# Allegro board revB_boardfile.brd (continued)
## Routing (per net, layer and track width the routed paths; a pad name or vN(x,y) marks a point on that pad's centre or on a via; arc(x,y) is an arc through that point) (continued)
GND: length 4.7
  BOTTOM w0.305: v1(27.11,56.13) C82.1 25.58,55.53 25.58,55.42 25.27,55.12 24.31,55.12 23.92,54.73 U14.4
  vias: v1(2.35,42.32) v1(2.35,41.69) v1(2.35,41.05) v1(3.11,42.32) v1(3.87,42.32) v1(4.76,42.32) v1(4.76,41.69) v1(4.76,41.05) v1(5.52,42.32) v1(6.29,42.32) v1(7.05,42.32) v1(7.05,41.69) v1(7.05,41.05) v1(9.21,55.53) v1(9.97,55.53) v1(10.86,55.53) v1(11.75,55.53) v1(12.64,56.68) v1(12.64,55.53) v1(14.41,57.31) v1(14.41,56.68) v1(15.18,57.31) v1(15.18,56.68) v1(16.82,50.04) v1(16.82,49.02) v1(17.45,50.04) v1(17.45,49.02) v1(18.22,50.07) v1(18.22,49.56) v1(18.22,49.06) v1(20.89,45.75) v1(21.53,45.75) v1(22.16,45.75) v1(22.54,52.93) v1(22.54,52.48) v1(22.54,52.04) v1(22.54,51.6) v1(22.54,51.15) v1(22.54,50.71) v1(22.8,45.75) v1(23.02,52.93) v1(23.02,52.48) v1(23.02,52.04) v1(23.02,51.6) v1(23.02,51.15) v1(23.02,50.71) v1(23.43,45.75) v1(23.49,52.93) v1(23.49,52.48) v1(23.49,52.04) v1(23.49,51.6) v1(23.49,51.15) v1(23.49,50.71) v1(24.07,45.75) v1(24.7,45.75) v1(25.34,45.75) v1(25.97,45.75) v1(26.61,45.75) v1(27.23,52.07) v1(27.23,51.43) v1(27.23,50.8) v1(27.23,50.16) v1(27.23,49.53) v1(27.23,48.89) v1(27.23,48.26) v1(27.23,47.62) v1(27.23,46.35) v1(27.24,45.75) v1(27.62,46.77) v1(27.88,45.75) v1(28.38,45.75)
AD9361_AUXADC: length 33.3
  BOTTOM w0.305: P1.5 39.18,29.12 34.23,29.12 33.59,29.75 33.59,34.45 29.53,38.51 22.03,38.51 20.51,36.99 18.73,36.99 17.36,35.62 P2.19
AD9361_AUXDAC1: length 35.1
  BOTTOM w0.305: P1.7 41.59,28.99 40.83,28.99 40.32,28.48 33.84,28.48 32.96,29.37 32.96,34.2 29.27,37.88 22.29,37.88 20.76,36.36 18.99,36.36 18.16,35.53 P2.21
AD9361_AUXDAC2: length 39
  BOTTOM w0.305: P2.23 18.96,35.42 19.27,35.72 21.14,35.72 22.67,37.24 29.02,37.24 32.32,33.94 32.32,29.12 33.59,27.85 40.7,27.85 41.21,28.35 42.99,28.35 44.26,29.62 44.26,30.89 43.75,31.4 43.75,32.16 P1.8
AD9361_GPO0: length 55.8
  L3_PWR w0.305: v1(13.36,36.74) 13.36,35.9 14.05,35.21 14.79,35.21 16.83,37.24 28.51,37.24 P1.1 36.13,31.15 36.13,31.91 36.64,32.42 36.64,35.97 42.61,41.94 42.61,43.34 47.31,48.04 48.7,48.04 v1(49.47,48.8)
  BOTTOM w0.203: U16.12 49.2,48.54 v1(49.47,48.8)
  BOTTOM w0.305: P2.9 v1(13.36,36.74)
AD9361_GPO0_5V: length 22.6
  BOTTOM w0.203: U16.11 48.7,49.06 49.21,49.56 57.8,49.56 58.71,48.65 58.71,41.49 57.28,40.05 U30.5
AD9361_GPO1: length 48
  L3_PWR w0.305: v1(47.31,48.65) 46.82,48.65 41.97,43.8 41.97,42.32 35.37,35.72 P1.2 34.23,32.93 29.27,37.88 16.11,37.88 v1(14.16,35.93)
  BOTTOM w0.203: v1(47.31,48.65) 47.7,48.25 U16.9
  BOTTOM w0.305: P2.11 v1(14.16,35.93)
AD9361_GPO1_5V: length 16.4
  BOTTOM w0.203: U30.1 52.41,36.84 45.4,43.85 45.4,46.26 46.15,47.01 U16.8
AD9361_GPO2: length 50.4
  L3_PWR w0.305: v1(48.2,43.72) 46.67,43.72 39.18,36.23 39.18,31.66 P1.3
  BOTTOM w0.203: v1(48.2,43.72) 48.2,43.73 U16.5
  BOTTOM w0.305: P2.13 14.96,35.35 17.23,37.63 20.26,37.63 21.78,39.15 30.03,39.15 34.48,34.7 35.88,34.7 36.51,34.07 36.51,31.78 P1.3
AD9361_GPO2_5V: length 15.9
  BOTTOM w0.203: 56.2,37.88 56.24,37.84 U30.6 ; 56.2,37.88 56.2,37.85 55.68,37.34 U30.2 ; 56.2,37.88 56.2,39.53 53.91,41.82 49.21,41.82 47.7,43.32 U16.6
AD9361_GPO3: length 50.3
  L3_PWR w0.305: v1(15.76,35.21) 17.16,36.61 27.88,36.61 32.96,31.53 32.96,30.51 34.35,29.12 36,29.12 36.64,29.75 36.64,31.66 P1.4 37.91,35.97 46.42,44.48 49.34,44.48 v1(49.97,43.85)
  BOTTOM w0.203: v1(49.97,43.85) 49.7,44.12 U16.2
  BOTTOM w0.305: P2.15 v1(15.76,35.21)
AD9361_GPO3_5V: length 90.9
  TOP w0.305: U6.2 v2(84.3,20.67) ; U11.2 v2(84.33,45.82)
  L3_PWR w0.508: v2(84.33,45.82) 82.93,44.42 76.45,44.42 69.85,37.82 65.47,37.82 v1(62.8,40.48) 61.21,42.07 50.42,42.07 v1(49.78,42.71)
  BOTTOM w0.203: U16.3 49.2,43.28 v1(49.78,42.71)
  BOTTOM w0.356: v2(84.3,20.67) 84.3,20.7 76.3,20.7 75.37,21.62 75.37,33.05 74.29,34.13 74.29,39.85 80.27,45.82 v2(84.33,45.82)
  BOTTOM w0.508: R29.2 64.07,35.76 64.07,39.21 v1(62.8,40.48)
RF_3V3: length 7.2
  BOTTOM w0.508: P2.12 14.16,27.7 13.9,27.43 13.36,27.43 ; R15.1 13.1,25.84 13.36,26.11 13.36,27.43 ; 13.36,27.43 P2.10
RF_5V0: length 5.2
  BOTTOM w0.457: 10.96,32.48 P2.3 ; 11.76,32.48 P2.5 ; P2.4 10.96,30.7 ; P2.6 11.76,30.7
RF_12V0: length 5.9
  BOTTOM w0.508: v1(24.56,27.86) P2.38 24.57,29.4 v1(24.57,30.77) v1(24.57,31.4) v1(24.57,32.04) 24.57,33.78 P2.37
  vias: v1(12.76,42.32) v1(12.76,41.69) v1(13.4,42.32) v1(13.4,41.69) v1(24.57,28.48)
RF_GPIO0: length 91.6
  L3_PWR w0.305: v1(39.31,43.09) 45.66,49.44 50.1,49.44 55.05,44.48 58.36,44.48 61.4,47.53 62.24,47.53 62.55,47.23 62.55,41.75 65.66,38.64 v1(67.12,38.64)
  BOTTOM w0.203: v1(67.12,38.64) 67.34,38.42 U4.3
  BOTTOM w0.305: P2.31 22.16,33.79 22.16,35.85 22.92,36.61 28.76,36.61 31.69,33.69 31.69,28.86 33.34,27.21 43.88,27.21 45.53,28.86 P1.9 44.39,31.53 44.39,38.01 v1(39.31,43.09)
RF_GPIO0_5V: length 33.8
  TOP w0.381: C57.1 C58.1 v2(68.76,56.16) 68.76,55.42 68.77,55.41
  BOTTOM w0.508: v2(68.76,56.16) 69.79,57.18 72.76,57.18 75.06,54.88 75.06,43.86 73.47,42.27 73.47,36.56 72.64,35.73 U15.6
RF_GPIO1: length 37.9
  BOTTOM w0.305: P2.33 22.96,35.38 23.56,35.97 28.51,35.97 31.05,33.43 31.05,28.61 33.08,26.58 44.39,26.58 46.8,28.99 46.8,31.66 P1.10
RF_GPIO1_5V: length 12.4
  TOP w0.254: C25.1 68.76,29.47 v2(68.77,29.46) 68.76,29.45 C28.1 68.76,27.07 R8.1
  BOTTOM w0.305: U15.4 68.63,35.33 68.93,35.02 70.15,35.02 70.74,34.44 70.74,33.31 70.36,32.93 69.72,32.93 69.28,32.48 69.28,29.97 v2(68.77,29.46)
RF_GPIO2: length 35.1
  BOTTOM w0.305: P1.11 48.07,28.86 45.15,25.94 32.83,25.94 30.42,28.35 30.42,33.18 28.26,35.34 24.07,35.34 23.76,35.03 P2.35
RF_GPIO_012_VDD: length 95.2
  L3_PWR w0.305: v1(71.31,40.34) 71.31,40.1 69.62,38.41 68.24,38.41 67.37,39.28 65.92,39.28 63.18,42.02 63.18,47.53 62.61,48.1 61.08,48.1 58.09,45.12 55.32,45.12 50.36,50.07 45.27,50.07 33.72,38.51 13.65,38.51 12.51,37.37 12.51,35.72 13.78,34.45 20.38,34.45 v1(21.14,35.21)
  BOTTOM w0.305: v1(21.14,35.21) 21.36,35 P2.29 ; U4.5 66.73,39.07 67.38,39.72 68.06,39.72 U4.1
  BOTTOM w0.356: C94.2 69.66,40.67 68.71,39.72 U4.1
  BOTTOM w0.406: v1(71.31,40.34) 71.64,40.67
  BOTTOM w0.508: C94.2 C93.2
RX: length 33.3
  TOP w0.305: 87.69,45.16 U11.4 ; 87.69,20.01 U6.4
  TOP w0.33: v2(89.86,20.06) 88.83,20.06 ; 88.83,20.06 C39.2 ; 88.83,20.06 L6.1 ; 88.83,20.06 88.15,20.06 88.1,20.01 87.69,20.01 ; v2(89.65,43.41) C69.2 L11.1 88.64,45.16 87.69,45.16
  L3_PWR w0.254: v2(89.86,20.06) 90.49,20.69 90.49,33.82 89.65,34.65 v2(89.65,43.41)
TX: length 5.7
  TOP w0.254: 80.43,50.95 T2.6
  TOP w0.33: 80.43,50.95 81.28,50.95 arc(82.76,50.34) 83.37,48.85 83.37,48.47 83.36,48.46 C65.1
UNNAMED_2_ADHMC546_I144_ACG: length 1.6
  TOP w0.305: U11.3 84.49,45.16
  TOP w0.33: 84.49,45.16 83.54,45.16 C66.1
UNNAMED_2_ADHMC546_I144_RFC: length 9
  TOP w0.305: U11.6 87.72,46.48
  TOP w0.33: U11.6 87.08,47.46 arc(86.94,47.81) L10.2 ; 88.98,46.45 88.84,46.31 ; 88.98,46.45 C71.1 ; 88.98,46.45 88.96,46.48 88.64,46.48 ; 88.84,46.31 C91.1 ; 88.84,46.31 L11.2 88.64,46.48 ; 88.64,46.48 87.72,46.48
UNNAMED_2_ADHMC546_I144_TX: length 3.5
  TOP w0.305: 85.08,46.48 84.49,46.48
  TOP w0.33: 84.49,46.48 C65.2 ; U11.1 85.08,46.48 85.08,47.4 arc(85.24,47.79) L10.1
UNNAMED_2_ADHMC669_I175_ACG: length 2.1
  TOP w0.254: C3.1 79.72,40.97 78.89,40.14 U7.6
UNNAMED_2_ADHMC669_I175_RES: length 2.2
  TOP w0.254: R2.1 78.39,40.34 U7.7
UNNAMED_2_ADHMC669_I175_RFIN: length 11.8
  TOP w0.254: 80.67,38.09 U7.3
  TOP w0.33: C69.1 88.84,42.14 88.84,40.55 arc(88.12,38.81) 86.38,38.09 80.67,38.09
UNNAMED_2_ADHMC669_I175_RFOUT: length 53.5
  TOP w0.254: 76.68,38.09 U7.10
  TOP w0.33: 76.68,38.09 53.63,38.09 53.62,38.11 D2.3 52.01,38.11 52,38.1 FL2.4
UNNAMED_2_ADHMC669_I175_VCTL: length 35.1
  TOP w0.203: U7.16 79.94,36.41 80.2,36.15 v2(80.2,35.72) C51.1
  L3_PWR w0.254: v2(80.2,35.72) 80.2,34.32 79.31,33.43 55.69,33.43 55.18,33.94 55.18,37.37 54.71,37.84 v1(53.78,37.84)
  BOTTOM w0.203: U30.3 v1(53.78,37.84)
UNNAMED_2_ADHMC669_I175_VDD: length 1.6
  TOP w0.254: U7.14 78.39,34.8 L8.1
UNNAMED_2_ADHMC921_I79_RFIN: length 1.1
  TOP w0.254: 65.63,50.19 U8.4
  TOP w0.33: 65.63,50.19 64.97,50.19 C52.2
UNNAMED_2_ADHMC921_I79_RFOUT: length 7.9
  TOP w0.254: C59.1 70.68,50.19 U8.15 ; U8.16 70.88,50.69 70.88,50.68 ; U8.17 70.93,51.19 70.93,51.19
  TOP w0.33: L9.1 71.83,50.96 C63.1 76.26,50.96
UNNAMED_2_ADHMC921_I79_VEN: length 1.8
  TOP w0.254: R4.2 68.75,54.11 U8.20
UNNAMED_2_ADL5324_I116_RFIN: length 3.7
  TOP w0.33: C42.2 C43.1 36.8,50.07 U10.1
UNNAMED_2_ADL5324_I116_RFOUT: length 23.8
  TOP w0.33: U10.3 41.27,50.17 41.29,50.19 L7.1 C49.1 62.41,50.19 C50.1 C52.1
UNNAMED_2_CAP_I99_N1: length 9.2
  TOP w0.33: FL1.2 24.53,46.9 arc(25.79,47.15) 26.86,47.86 28.17,49.17 arc(29.17,49.84) 30.34,50.07 C42.1
UNNAMED_2_CAP_I148_N2: length 4
  TOP w0.33: C71.2 93.58,46.5 RF_IO1.1
UNNAMED_2_CAP_I196_N2: length 1.7
  TOP w0.254: 78.73,50.95 T2.1
  TOP w0.33: 78.73,50.95 77.52,50.95 C64.2
UNNAMED_2_CNBNC3P_I83_CNTR: length 11.1
  TOP w0.33: TX1_A.1 FL1.4
UNNAMED_2_CNBNC3P_I86_CNTR: length 51.9
  TOP w0.305: R13.1 54.25,44.99
  TOP w0.33: TX1MON.1 7.82,42.45 arc(9.55,42.79) 11.01,43.77 arc(12.36,44.67) 13.95,44.99 54.25,44.99 ; R14.1 54.3,45.02 R13.1
UNNAMED_2_CNBNC3P_I158_CNTR: length 11.2
  TOP w0.33: RX1_A.1 10.22,38.1 FL2.2
UNNAMED_2_RES_I197_N1: length 1.7
  TOP w0.254: 79.97,49.62 T2.4
  TOP w0.33: R18.1 79.97,49.09 79.97,49.1 79.97,49.62
UNNAMED_2_RES_I198_N2: length 22.9
  TOP w0.254: T2.3 79.19,49.62
  TOP w0.33: R14.2 58.03,45.03 R16.1 60.02,45.04 70.34,45.04 arc(74.88,46.24) 78.73,48.93 79.02,49.23 arc(79.14,49.41) 79.19,49.62
UNNAMED_3_ADHMC546_I36_ACG: length 1.5
  TOP w0.305: 84.39,20.01 U6.3
  TOP w0.33: C36.1 83.54,20.01 84.39,20.01
UNNAMED_3_ADHMC546_I36_RFC: length 8.5
  TOP w0.305: 87.62,21.33 U6.6 87.03,21.75
  TOP w0.33: C40.1 88.84,21.33 ; 88.84,21.33 88.84,21.19 L6.2 ; 88.84,21.33 87.62,21.33 ; 88.84,21.33 C41.1 ; 87.03,21.75 87.03,22.25 arc(86.87,22.63) L5.2
UNNAMED_3_ADHMC546_I36_TX: length 3.4
  TOP w0.305: 84.47,21.33 U6.1 85.03,21.74
  TOP w0.33: C35.2 84.47,21.33 ; 85.03,21.74 85.03,22.29 arc(85.18,22.64) L5.1
UNNAMED_3_ADHMC669_I19_ACG: length 2.1
  TOP w0.254: C1.1 79.85,11.91 78.92,10.98 U2.6
UNNAMED_3_ADHMC669_I19_RES: length 2.2
  TOP w0.254: U2.7 78.42,11.39 R1.1
UNNAMED_3_ADHMC669_I19_RFIN: length 15
  TOP w0.254: 80.69,9.04 U2.3
  TOP w0.33: 80.69,9.04 84.76,9.04 arc(87.64,10.23) 88.84,13.11 88.84,17.02 C39.1
UNNAMED_3_ADHMC669_I19_RFOUT: length 53.8
  TOP w0.254: U2.10 76.53,9.04 76.52,9.02
  TOP w0.33: FL4.4 46.39,9.05 D1.3 76.52,9.02
UNNAMED_3_ADHMC669_I19_VCTL: length 55.6
  TOP w0.203: v2(79.82,4.88) 80.07,5.14 C14.1 79.74,6.1 79.74,6.56 79.42,6.89 U2.16
  BOTTOM w0.254: 66.48,3.59 78.52,3.59 v2(79.82,4.88)
  BOTTOM w0.305: 66.48,3.59 56.2,13.88 56.2,36.99 56.55,37.34 U30.7
UNNAMED_3_ADHMC669_I19_VDD: length 1.6
  TOP w0.254: U2.14 78.42,6.4 78.39,6.37 L3.1
UNNAMED_3_ADHMC921_I94_RFIN: length 1.1
  TOP w0.254: 65.63,21.85 U5.4
  TOP w0.33: 65.63,21.85 64.97,21.85 C15.2
UNNAMED_3_ADHMC921_I94_RFOUT: length 7.8
  TOP w0.254: U5.17 70.9,22.85 70.92,22.83 70.92,22.84 ; U5.16 70.76,22.35 ; U5.15 70.68,21.85 C29.1
  TOP w0.33: 71.61,22.61 C33.1 76.26,22.61
UNNAMED_3_ADHMC921_I94_VEN: length 1.8
  TOP w0.254: R8.2 68.75,25.77 U5.20
UNNAMED_3_ADL5324_I56_RFIN: length 3.7
  TOP w0.33: U9.1 35.89,21.85 C6.1 C5.2
UNNAMED_3_ADL5324_I56_RFOUT: length 24
  TOP w0.33: C15.1 C13.1 C12.1 L2.1 40.97,21.85 40.97,21.85 U9.3
UNNAMED_3_CAP_I35_N1: length 3.4
  TOP w0.254: 80.49,22.6 T1.6
  TOP w0.33: C35.1 80.49,22.6
UNNAMED_3_CAP_I45_N2: length 3.9
  TOP w0.33: RF_IO2.1 C41.2
UNNAMED_3_CAP_I53_N1: length 8.2
  TOP w0.33: FL3.2 C5.1
UNNAMED_3_CAP_I127_N2: length 1.6
  TOP w0.254: T1.1 78.69,22.6 78.68,22.61
  TOP w0.33: 78.68,22.61 C34.2
UNNAMED_3_CNBNC3P_I21_CNTR: length 46.2
  TOP w0.33: TX2MON.1 54.2,17.43 R5.1 56.15,17.52 R6.1
UNNAMED_3_CNBNC3P_I51_CNTR: length 16
  TOP w0.33: TX2_A.1 FL3.4
UNNAMED_3_CNBNC3P_I105_CNTR: length 17
  TOP w0.33: RX2_A.1 7.59,12.99 arc(10.14,12.48) 12.3,11.04 12.53,10.81 arc(14.48,9.51) 16.78,9.05 FL4.2
UNNAMED_3_RES_I126_N1: length 1.7
  TOP w0.254: 79.95,21.3 T1.4
  TOP w0.33: R9.1 79.95,20.75 79.95,20.75 79.95,21.3
UNNAMED_3_RES_I129_N1: length 22.4
  TOP w0.254: 78.6,21.29 78.89,21.59 T1.3
  TOP w0.33: R6.2 59.84,17.43 R7.1 59.89,17.41 70.22,17.41 arc(74.75,18.61) 78.6,21.29
UNNAMED_5_7445V2_I198_B: length 2.1
  BOTTOM w0.406: U4.4 65.25,37.85 R28.1
UNNAMED_5_ADM7171_I71_SS: length 2.1
  BOTTOM w0.305: U1.4 83.18,55.95 C2.1
UNNAMED_5_ADM7171_I103_SS: length 2.1
  BOTTOM w0.305: U12.4 83.18,28.75 83.36,28.93 C76.1
UNNAMED_5_ADP238X_I108_BST: length 7.5
  L3_PWR w0.305: v1(23.92,48.93) 23.29,48.29 21.12,48.29 v1(19.49,46.67)
  BOTTOM w0.305: C81.1 v1(19.49,46.67) ; U14.15 v1(23.92,48.93)
UNNAMED_5_ADP238X_I108_COMP: length 6.8
  BOTTOM w0.305: C86.1 17.35,56.19 18.18,55.37 18.18,55.22 18.91,54.48 C84.1 19.81,53.72 19.96,53.86 U14.1
UNNAMED_5_ADP238X_I108_EN: length 17
  BOTTOM w0.305: U14.20 12.76,51.06 11.86,50.16 R23.2 R21.2
UNNAMED_5_ADP238X_I108_FB: length 4.6
  BOTTOM w0.305: U14.2 22.92,54.6 22.34,55.18 R24.1 22.34,57.44 22.28,57.5 R25.2
UNNAMED_5_ADP238X_I108_PVIN1: length 8.2
  BOTTOM w0.305: C19.1 13.39,49.53 12.75,48.89 R23.1
UNNAMED_5_ADP238X_I108_RT: length 12.5
  BOTTOM w0.305: R22.1 10.28,51.69 20.25,51.69 20.62,52.06 U14.22
UNNAMED_5_ADP238X_I108_SS: length 10.5
  BOTTOM w0.305: C80.1 12.27,52.7 12.65,52.32 19.86,52.32 20.61,53.06 U14.24
UNNAMED_5_ADP238X_I108_SW1: length 11.8
  L3_PWR w0.305: v1(19.49,44.99) 19.49,45.88 21.27,47.66 23.56,47.66 v1(24.57,48.67)
  BOTTOM w0.305: v1(19.49,44.99) 19.27,44.76 C81.2 ; U14.PAD2 24.42,51.69 U14.14 24.42,48.82 v1(24.57,48.67)
UNNAMED_5_ADP238X_I108_VREG: length 2.7
  BOTTOM w0.305: C82.2 24.47,56.08 23.42,55.03 U14.3
UNNAMED_5_ADP7104_I52_SENSE: length 4.5
  BOTTOM w0.305: R10.2 81.13,42.46 81.08,42.42 R12.1 81.13,41.62 82.36,40.39 U3.2
UNNAMED_5_ADP7104_I92_SENSE: length 4.6
  BOTTOM w0.305: R19.2 81,13.16 81.08,13.08 R20.1 81.13,12.28 82.23,11.18 U13.2
UNNAMED_5_CAP_I117_N2: length 27.6
  L3_PWR w0.305: v1(19.36,56.13) 19.36,57.3 21.27,59.22 28.38,59.22 34.68,52.92 v1(34.68,49.69)
  BOTTOM w0.305: R27.2 C83.2 v1(34.68,49.69) ; R24.2 v1(19.36,56.13)
UNNAMED_5_CAP_I127_N2: length 2.5
  BOTTOM w0.305: C84.2 15.55,53.72 15.48,53.65 R26.1
UNNAMED_5_CAP_I146_N2: length 2.5
  BOTTOM w0.305: R3.1 16.88,39.4 16.84,39.37 C92.2
UNNAMED_5_DIOLED_I85_P: length 11.5
  TOP w0.305: DS1.A v2(2.72,29.76)
  BOTTOM w0.305: R15.2 10.21,26.07 6.41,26.07 v2(2.72,29.76)
UNNAMED_5_NC7WZ17P6X_I161_A1: length 6.2
  BOTTOM w0.305: 68.56,33.9 U15.3 ; 68.56,33.9 67.63,33.9 R29.1 ; 68.56,33.9 68.64,33.99 68.64,34.2 68.92,34.48 69.65,34.48 69.93,34.2 U15.1
  BOTTOM w0.406: R29.1 R28.2
VDET_HMC921_1: length 68.3
  TOP w0.254: C56.1 68.75,47.17 U8.11
  TOP w0.305: C56.1 62.17,47.15 v2(61.91,46.9)
  L3_PWR w0.305: v1(19.76,35.21) 20.52,35.97 27.37,35.97 32.07,31.28 32.07,30.26 33.97,28.35 36.51,28.35 37.27,29.12 41.08,29.12 41.72,29.75 41.72,37.75 45.78,41.82 48,41.82 49.53,43.34 58.36,43.34 v2(61.91,46.9)
  BOTTOM w0.305: P2.25 v1(19.76,35.21)
VDET_HMC921_2: length 56.5
  TOP w0.254: U5.11 68.75,18.98 C24.1
  TOP w0.305: v2(51.13,19.7) 60.56,19.7 61.43,18.83 68.64,18.83 C24.1
  BOTTOM w0.305: v2(51.13,19.7) 26.37,19.7 19.76,26.31 P2.26

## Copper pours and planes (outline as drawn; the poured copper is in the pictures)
5V5 on BOTTOM: 85.66,7.91 85.66,9.05 85.79,9.18 85.79,10.83 86.93,10.83 87.44,10.32 90.74,10.32 90.74,12.35 90.23,12.86 90.23,24.8 85.79,24.8 85.79,26.7 87.18,26.7 87.18,28.48 90.61,28.48 90.61,37.12 85.79,37.12 85.79,40.04 86.55,40.04 86.55,39.78 86.93,39.4 90.74,39.4 90.74,42.45 90.99,42.71 90.99,51.09 85.79,51.09 85.79,53.12 87.18,53.12 87.18,54.9 90.74,54.9 90.74,58.58 59.47,58.58 53.38,52.48 38.54,52.48 37.02,50.96 37.02,41.92 35.99,40.89 20.63,40.89 20.63,42.67 29.52,42.67 29.52,43.81 32.95,43.81 32.95,46.1 35.1,46.1 35.1,57.15 34.85,57.4 32.69,57.4 32.6,57.31 25.97,57.31 25.97,61.25 92.9,61.25 92.9,7.91
5V_3P3V_LNA1 on TOP: 74.48,34.07 77.41,34.07 77.41,35.59 76.26,35.59 76.26,36.86 75.75,37.37 74.48,37.37
5V_3P3V_LNA1 on BOTTOM: 58.48,36.99 56.7,36.99 56.7,34.7 57.34,34.07 62.42,34.07 62.93,34.58 62.93,36.86 62.42,37.37 58.48,37.37
5V_3P3V_LNA1 on BOTTOM: 83.5,39.91 83.5,36.86 82.87,36.23 80.07,36.23 80.07,34.32 79.82,34.07 75.25,34.07 74.67,34.64 74.67,38.26 79.44,38.26 79.44,40.17 79.69,40.42 81.85,40.42 82.23,40.04 83.37,40.04
5V_3P3V_LNA1 on L3_PWR: 55.94,38.7 55.94,34.07 88.45,34.07 88.84,34.45 88.84,39.53 88.33,40.04 86.8,40.04 83.37,43.47 76.01,43.47 70.29,37.75 65.28,37.75 63.37,39.66 56.89,39.66
5V_3P3V_LNA2 on TOP: 74.48,8.44 74.48,4.88 77.28,4.88 77.28,6.54 76.39,6.54 76.39,7.15 75.75,7.78 75.75,8.44
5V_3P3V_LNA2 on BOTTOM: 79.56,11.08 81.85,11.08 82.1,10.83 83.37,10.83 83.37,7.78 82.61,7.02 79.69,7.02 79.69,5.37 79.06,4.73 74.87,4.73 74.23,5.37 74.23,8.8 74.48,9.05 79.18,9.05 79.18,10.7
5V_3P3V_LNA2 on L3_PWR: 83.25,10.7 83.25,7.78 79.95,4.48 71.94,4.48 71.94,10.7
5V_PREAMP1 on TOP (solid shape): 76.77,56.04 73.79,56.04 73.79,56.07 73.09,56.07 73.09,56.93 73.09,57.44 73.09,58.07 76.77,58.07
5V_PREAMP1 on TOP: 86.23,42.26 86.23,43.98 87.88,43.98 87.88,40.67 86.55,40.67 86.55,41.94
5V_PREAMP1 on TOP: 67.12,53.37 65.34,53.37 64.83,53.88 64.83,56.42 64.45,56.8 64.45,59.09 66.61,59.09 67.12,58.58
5V_PREAMP1 on TOP: 40.32,57.95 40.32,56.04 41.46,54.9 41.46,51.21 42.48,51.21 42.48,55.53 42.86,55.91 42.86,58.2 42.61,58.45 40.83,58.45
5V_PREAMP1 on BOTTOM: 53.02,46.77 53.02,45.63 57.09,45.63 57.09,46.77
5V_PREAMP1 on BOTTOM: 83.5,53.63 83.5,48.55 78.68,48.55 78.68,53.63
5V_PREAMP1 on BOTTOM: 66.6,44.27 64.82,44.27 64.82,40.97 65.34,40.44 65.34,39.57 66.6,39.57
5V_PREAMP1 on L3_PWR: 88.84,41.56 88.33,41.05 86.8,41.05 85.03,42.83 85.03,46.01 84.64,46.39 84.01,46.39 82.87,45.25 76.01,45.25 69.91,39.15 66.1,39.15 63.75,41.5 63.75,47.34 62.8,48.29 61.4,48.29 58.36,45.25 56.7,45.25 56.51,45.44 56.07,45.44 51.05,50.45 44.77,50.45 42.23,47.91 38.92,47.91 38.92,61.25 87.95,61.25 88.84,60.36 ; 1 cut-out
5V_PREAMP2 on TOP (solid shape): 76.77,27.72 73.79,27.72 73.79,27.72 73.09,27.72 73.09,28.58 73.09,29.09 73.09,29.75 76.77,29.75
5V_PREAMP2 on TOP: 86.55,15.53 86.55,18.7 88.07,18.7 88.07,15.53
5V_PREAMP2 on TOP: 67.11,25.02 65.33,25.02 64.82,25.52 64.82,28.11 64.44,28.49 64.44,30.51 66.74,30.51 67.11,30.14
5V_PREAMP2 on TOP: 41.08,22.89 41.08,28.1 41.72,28.74 46.04,28.74 46.42,28.35 46.42,26.45 45.15,26.45 44.26,27.34 42.48,27.34 42.23,27.08 42.23,24.04 42.29,23.97 42.29,23.85 42.1,23.66 42.1,22.89
5V_PREAMP2 on BOTTOM: 83.5,27.08 83.5,22.51 78.8,22.51 78.8,27.21 82.61,27.21 82.74,27.08
5V_PREAMP2 on L3_PWR: 83.56,17.05 85.47,15.15 87.82,15.15 88.07,15.4 88.07,20.99 87.57,21.5 83.25,21.5 82.74,22 82.74,26.96 82.23,27.47 77.28,27.47 74.99,29.75 67.88,29.75 67.12,30.51 66.1,30.51 64.2,28.61 39.43,28.61 38.42,27.59 38.42,17.56 38.92,17.05 ; 4 cut-outs
AGND on TOP: 96.07,0.67 4,0.67 0.67,4 0.67,58.17 3.75,61.25 96.33,61.25 99.25,58.33 99.25,3.84 ; 24 cut-outs
AGND on BOTTOM: 90.87,41.44 87.69,41.44 87.31,41.05 85.66,41.05 85.28,41.44 85.28,40.29 85.66,40.67 86.93,40.67 86.93,39.91 87.06,39.78 90.87,39.78
AGND on BOTTOM: 4,0.67 0.65,4.02 0.65,40.17 36.26,40.17 37.78,41.69 37.78,50.45 38.92,51.6 53.53,51.6 63.18,61.25 96.33,61.25 99.25,58.33 99.25,3.84 96.07,0.67 ; 25 cut-outs
AGND on L2_GND: 96.07,0.67 4,0.67 0.65,4.02 0.65,58.15 3.75,61.25 96.33,61.25 99.25,58.33 99.25,3.84 ; 2 cut-outs
AGND on L3_PWR: 4,0.67 0.65,4.02 0.65,40.17 8.06,40.17 8.06,28.35 9.71,26.7 25.08,26.7 25.72,27.34 25.72,33.18 25.34,33.56 23.81,33.56 23.18,32.93 23.18,31.02 22.8,30.64 13.02,30.64 12.64,31.02 12.64,33.05 11.49,34.2 11.49,39.28 12.38,40.17 24.45,40.17 32.57,32.04 32.57,28.99 33.72,27.85 36.38,27.85 37.4,26.83 37.4,16.8 37.91,16.29 83.5,16.29 83.5,27.47 82.23,28.74 77.28,28.74 75.37,30.64 65.09,30.64 64.2,29.75 48.58,29.75 48.7,29.88 47.43,31.15 44.39,31.15 42.23,33.31 42.23,37.75 45.91,41.44 53.4,41.44 55.5,39.34 60.32,39.34 64.45,43.47 82.99,43.47 86.17,40.29 88.84,40.29 88.84,58.96 91.12,61.25 96.33,61.25 99.25,58.33 99.25,3.84 96.07,0.67 ; 2 cut-outs
GND on BOTTOM: 16.46,50.47 16.46,48.66 16.49,48.64 18.57,48.64 18.57,50.44 18.54,50.47
GND on BOTTOM: 28.68,43.74 20.68,43.74 20.68,46.12 24.23,46.12 24.23,48.05 24.87,48.05 24.87,50.26 25.33,50.26 25.33,52.65 25.35,52.68 29.39,52.68 29.39,46.99 28.68,46.28
GND on BOTTOM: 21.52,58.8 21.52,57.66 21.26,57.4 15.93,57.4 15.55,57.02 15.55,54.86 13.39,54.86 12.12,53.59 6.66,53.59 6.66,53.63 6.41,53.63 6.16,53.37 6.16,48.42 7.43,47.15 7.43,40.67 0.65,40.67 0.65,50.4 9.17,58.93 21.39,58.93
GND on L3_PWR: 20.38,46.13 20.38,43.98 20.89,43.47 30.42,43.47 31.3,44.36 31.3,55.15 28.76,57.69 22.29,57.69 20.13,55.53 18.6,55.53 16.32,57.82 9.21,57.82 8.24,57.99 0.65,50.4 0.65,40.67 7.43,40.67 7.43,46.13 9.33,48.04 18.73,48.04 20.64,49.94 24.83,49.94 25.46,49.31 25.46,47.53 24.83,46.9 21.14,46.9
(no net) on TOP: 71.18,58.07 72.58,58.07 72.58,56.29 72.33,56.04 72.33,51.72 71.18,51.72
(no net) on TOP: 71.18,29.75 72.58,29.75 72.58,27.97 72.33,27.72 72.33,23.38 71.18,23.38
(no net) on TOP: 76.77,27.72 76.77,29.75 73.09,29.75 73.09,27.72
(no net) on TOP: 76.77,56.04 76.77,58.07 73.09,58.07 73.09,56.04
RF_5V0 on BOTTOM: 10.59,33.31 10.59,28.74 12.12,28.74 12.12,30.77 12,30.88 12,33.31
RF_12V0 on BOTTOM: 16.83,45.25 16.83,41.18 12.38,41.18 12.38,45.25
RF_12V0 on L3_PWR: 25.21,33.18 25.21,27.47 24.95,27.21 10.22,27.21 9.08,28.35 9.08,32.67 8.44,33.31 8.44,42.83 9.33,43.72 14.16,43.72 14.79,43.09 14.79,42.2 13.65,41.05 11.37,41.05 10.86,40.55 10.86,33.82 12,32.67 12,30.77 12.64,30.13 23.05,30.13 23.81,30.89 23.81,32.8 24.19,33.18
UNNAMED_2_ADHMC921_I79_RFOUT on TOP: 72.05,50.86 71.56,51.34 70.55,51.34 70.55,50.07 71.26,50.07
UNNAMED_2_CAP_I54_N1 on TOP (solid shape): 72.58,57.44 72.58,56.93 72.58,56.29 72.33,56.04 72.33,51.72 71.18,51.72 71.18,58.07 72.58,58.07
UNNAMED_3_ADHMC921_I94_RFOUT on TOP: 71.71,22.12 71.71,22.76 71.45,23.01 70.56,23.01 70.56,21.69 71.27,21.69
UNNAMED_3_CAP_I91_N1 on TOP (solid shape): 72.58,29.09 72.58,28.58 72.58,27.97 72.33,27.72 72.33,23.38 71.18,23.38 71.18,29.75 72.58,29.75
UNNAMED_5_ADP238X_I108_PVIN1 on BOTTOM: 16.18,46.48 14.28,46.48 14.28,50.42 14.35,50.49 15.88,50.49 15.9,50.47 15.9,48.33 18.9,48.33 18.9,50.34 19.2,50.65 22.07,50.65 22.07,50.19 22.1,50.16 23.55,50.16 23.55,46.48 23.52,46.45 20.58,46.45 19.48,47.55 16.28,47.55 16.18,47.44
UNNAMED_5_ADP238X_I108_SW1 on BOTTOM: 24.13,50.52 24.13,53.06 24.33,53.26 24.33,54.61 25.58,54.61 25.99,55.01 27.94,55.01 28.07,55.14 28.07,56.92 29.47,56.92 29.49,56.89 29.49,53.29 26.57,53.29 26.27,52.98 24.94,52.98 24.94,50.52
UNNAMED_5_CAP_I117_N1 on BOTTOM: 30.48,56.94 30.48,47.37 29.52,46.4 29.52,45.54 29.54,45.51 32.01,45.51 32.03,45.54 32.03,46.33 32.11,46.4 32.11,50.8 34.29,50.8 34.32,50.82 34.32,56.61 33.96,56.97 30.51,56.97

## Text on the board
User.Comments: ASSEMBLY
TOP: AD-PZSDR2400TDD-EBZ
Ref Des/Assembly Top: PRIMARY SIDE
Ref Des/Silkscreen Top: GND | 5V5 | 040367 REV B
DIMENSION: 2.284 | -.156 | "0" | 3.937 | REF | 2.440 | 4 PLACES | 3.779 | +2/-0 MILS | DIA MAX | SEE NOTE #15
PAGE_OUTLINE: B | ECR-055271 | 15MAY15 | 14AUG15 | C.E. | EVAL BOARD Z | 02-040367
User.8: 08-      -07 | L2_GND
User.9: L3_PWR | 08-      -08
User.12: 50OHMS | 4
User.35: FIGURE | SIZE | 8.0 | PLATED | FINISHED HOLES IN MILS | ALL UNITS ARE IN MILS | QTY | 2575 | TOLERANCE/NOTES
User.36: 2 | DRILLED HOLES LAYER 1 TO LAYER 2 | DIA MAX | SEE NOTE #15
User.37: 3 | DRILLED HOLES LAYER 3 TO LAYER 4. | DIA MAX | SEE NOTE #15
User.38: 4 | DRILLED HOLES LAYER 23 TO LAYER 24
User.43: FIGURE | SIZE | 8.0 | 40.0 | 45.0 | 31.0 | 47.0 | 155.0 | PLATED | NON-PLATED | FINISHED HOLES IN MILS | ALL UNITS ARE IN MILS | QTY | 813 | 2 | 12 | 1 | 6 | TOLERANCE/NOTES
User.44: FIGURE | SIZE | 8.0 | PLATED | FINISHED HOLES IN MILS | ALL UNITS ARE IN MILS | QTY | 157 | TOLERANCE/NOTES
